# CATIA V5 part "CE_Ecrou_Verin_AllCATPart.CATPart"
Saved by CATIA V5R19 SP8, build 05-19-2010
Part number: CE6_Ecrou_Verin_AllCATPart
Bounding box of the stored display mesh (mm): x -51 to -15, y 118.18 to 212.921, z -15.775 to 101.546
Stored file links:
  D:\Documents\1_Travail\1 - ac-limoges.fr\ac-limoges.fr\Emmanuel Maynard - STI2D_Turgot\2 -2I2D\1_SEQUENCE_ Tapis_de_course\3- Spécificités\Spé_ITEC\3-Pente\Tapis_TC520B_Pente\CE_Ecrou_Verin_AllCATPart.CATPart
  D:\Documents\1_Travail\1 - ac-limoges.fr\ac-limoges.fr\Emmanuel Maynard - STI2D_Turgot\2 -2I2D\1_SEQUENCE_ Tapis_de_course\3- Spécificités\Spé_ITEC\3-Pente\Tapis_TC520B_Pente\CE_Vis_AllCATPart.CATPart
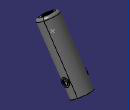
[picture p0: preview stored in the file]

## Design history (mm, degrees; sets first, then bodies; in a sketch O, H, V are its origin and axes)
AxisSystem1: origin (0, 0, 0), X (1, 0, 0), Y (0, 1, 0), Z (0, 0, 1)
Body1 (main body)
  Plane1: type OffsetPt, RefPlane YZ plane of AxisSystem1, RefPoint {point type Center, Curve edge [face of Solid1 | face of Solid1]}
  Sketch1 on Plane1, origin (-33, 156.7245, 95.7677), H (0, 0.7367, 0.6762), V (0, -0.6762, 0.7367)
    point P1 (-28.0319, -8.7154)
    reference projected line E1 through (-25.3406, 4.9798) direction (-0.1928, -0.9812)
    coincidence: P1 E1
Body2 "CE_Ecrou_Verin.1\\Corps principal"
  Solid1: solid without history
